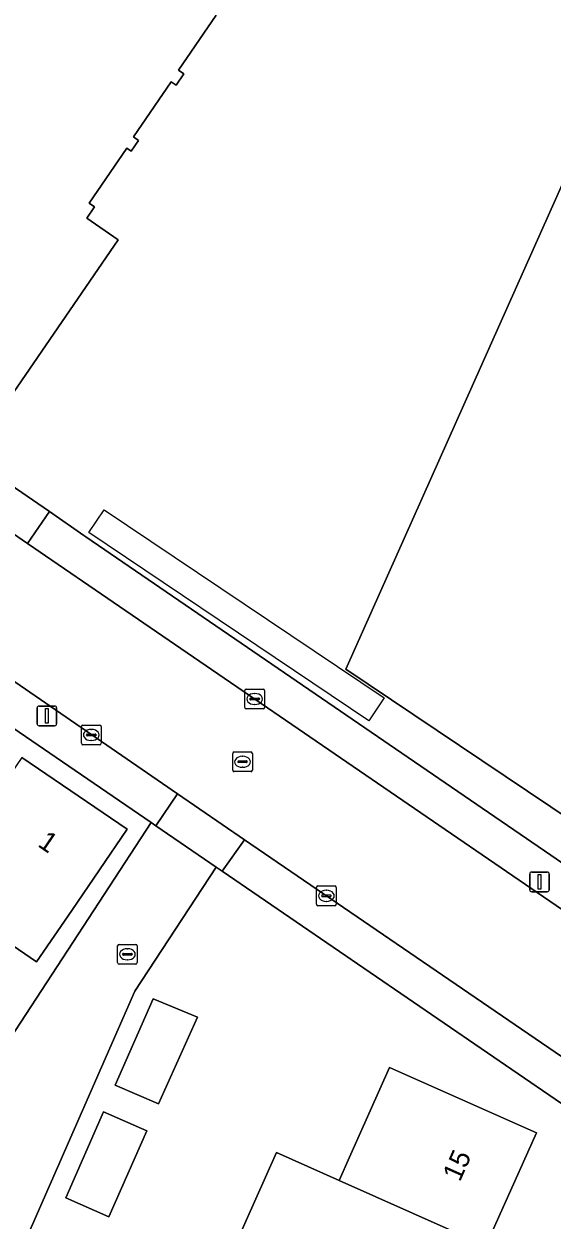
# Model space of a CAD drawing. Extents: x 160023 to 161302, y 384750 to 385707.
# Drawn here: x 160123.2 to 160150, y 385310.5 to 385371.2 of the extents above; entities that cross this region are included whole.
import ezdxf

# ---------------------------------------------------------------- set-up
doc = ezdxf.new("R2010")
doc.units = 0
for name, color, linetype in [('IMGEO_Erf', 7, 'Continuous'), ('IMGEO_Kolk', 7, 'Continuous'), ('IMGEO_Lichtmast', 7, 'Continuous'), ('IMGEO_Muur', 7, 'Continuous'), ('IMGEO_Pand', 7, 'Continuous'), ('IMGEO_Pand_nummerreeks', 7, 'Continuous'), ('IMGEO_Rijbaan_lokaal_open', 7, 'Continuous'), ('IMGEO_Rioolput', 7, 'Continuous'), ('IMGEO_Voetpad_open', 7, 'Continuous')]:
    doc.layers.add(name, color=color, linetype=linetype)

msp = doc.modelspace()

# ---------------------------------------------------------------- linework, layer by layer
at = {"layer": 'IMGEO_Erf'}
for points in [[(160132.919, 385371.685), (160131.005, 385368.893), (160131.279, 385368.705), (160130.884, 385368.13), (160130.634, 385368.301), (160128.713, 385365.499), (160128.973, 385365.32), (160128.601, 385364.779), (160128.386, 385364.926), (160126.471, 385362.132), (160126.738, 385361.949), (160126.341, 385361.37), (160127.943, 385360.271), (160122.625, 385352.516), (160109.571, 385361.468), (160114.265, 385368.313), (160113.654, 385368.732), (160114.009, 385369.25), (160112.687, 385370.157), (160124.902, 385387.961)], [(160093.406, 385374.95), (160103.841, 385367.794), (160103.323, 385367.037), (160102.919, 385366.448), (160100.498, 385362.918), (160105.594, 385359.428), (160120.662, 385349.43), (160120.442, 385349.221), (160124.446, 385346.473), (160126.203, 385345.256), (160126.296, 385345.192), (160149.901, 385329.017), (160154.104, 385326.136), (160157.93, 385334.826), (160155.989, 385335.681), (160153.709, 385336.675), (160151.041, 385330.714), (160139.497, 385338.47), (160150.705, 385363.58)], [(160118.455, 385313.614), (160129.62, 385330.68), (160087.038, 385359.824)], [(160123.055, 385333.992), (160128.399, 385330.342), (160125.58, 385326.215), (160123.798, 385323.607), (160120.717, 385325.711)], [(160152.014, 385315.353), (160133.213, 385328.221), (160132.92, 385328.421), (160128.791, 385322.11), (160120.909, 385304.204), (160118.514, 385298.764), (160117.264, 385295.926), (160116.015, 385293.089), (160114.766, 385290.253), (160113.701, 385287.743), (160114.618, 385287.345), (160116.68, 385286.451), (160114.754, 385282.009), (160113.13, 385278.262), (160115.091, 385275.318), (160112.419, 385273.539), (160114.46, 385270.474), (160117.839, 385265.396), (160112.507, 385262.087), (160109.628, 385266.727), (160106.437, 385271.869)], [(160133.385, 385308.118), (160135.973, 385313.924), (160139.16, 385312.503), (160139.685, 385313.681), (160141.719, 385318.246), (160149.173, 385314.924), (160146.613, 385309.181)]]:
    msp.add_lwpolyline(points, dxfattribs=at)
for points in [[(160129.712, 385321.73), (160131.965, 385320.799), (160129.993, 385316.404), (160127.791, 385317.345)], [(160127.192, 385315.989), (160129.39, 385315.025), (160127.473, 385310.658), (160125.275, 385311.622)]]:
    msp.add_lwpolyline(points, close=True, dxfattribs=at)
at = {"layer": 'IMGEO_Kolk'}
for p, q in [((160134.369, 385336.53), (160134.369, 385337.382)), ((160134.444, 385337.456), (160135.296, 385337.456)), ((160134.857, 385337.236), (160134.882, 385337.236)), ((160135.37, 385337.382), (160135.37, 385336.53)), ((160134.628, 385336.95), (160134.628, 385336.962)), ((160135.066, 385336.913), (160134.668, 385336.913)), ((160134.671, 385336.999), (160135.069, 385336.999)), ((160134.88, 385336.676), (160134.855, 385336.676)), ((160135.112, 385336.962), (160135.112, 385336.95)), ((160135.296, 385336.456), (160134.444, 385336.456)), ((160126.071, 385334.705), (160126.071, 385335.557)), ((160126.146, 385335.631), (160126.998, 385335.631)), ((160126.559, 385335.411), (160126.584, 385335.411)), ((160127.072, 385335.557), (160127.072, 385334.705)), ((160126.33, 385335.125), (160126.33, 385335.137)), ((160126.768, 385335.088), (160126.37, 385335.088)), ((160126.373, 385335.174), (160126.771, 385335.174)), ((160126.582, 385334.851), (160126.557, 385334.851)), ((160126.814, 385335.137), (160126.814, 385335.125)), ((160126.998, 385334.631), (160126.146, 385334.631)), ((160138.009, 385326.534), (160138.009, 385327.386)), ((160138.084, 385327.46), (160138.936, 385327.46)), ((160138.268, 385326.954), (160138.268, 385326.966)), ((160138.706, 385326.917), (160138.308, 385326.917)), ((160138.311, 385327.003), (160138.709, 385327.003)), ((160138.497, 385327.24), (160138.522, 385327.24)), ((160138.752, 385326.966), (160138.752, 385326.954)), ((160139.01, 385327.386), (160139.01, 385326.534)), ((160138.936, 385326.46), (160138.084, 385326.46)), ((160138.52, 385326.68), (160138.495, 385326.68)), ((160127.983, 385324.492), (160128.835, 385324.492)), ((160127.908, 385323.566), (160127.908, 385324.418)), ((160128.167, 385323.986), (160128.167, 385323.998)), ((160128.605, 385323.949), (160128.207, 385323.949)), ((160128.21, 385324.035), (160128.608, 385324.035)), ((160128.396, 385324.272), (160128.421, 385324.272)), ((160128.651, 385323.998), (160128.651, 385323.986)), ((160128.909, 385324.418), (160128.909, 385323.566)), ((160128.835, 385323.492), (160127.983, 385323.492)), ((160128.419, 385323.712), (160128.394, 385323.712))]:
    msp.add_line(p, q, dxfattribs=at)
for points in [[(160134.369, 385336.53), (160134.369, 385337.382)], [(160134.444, 385337.456), (160135.296, 385337.456)], [(160135.37, 385337.382), (160135.37, 385336.53)], [(160135.296, 385336.456), (160134.444, 385336.456)], [(160126.071, 385334.705), (160126.071, 385335.557)], [(160126.146, 385335.631), (160126.998, 385335.631)], [(160127.072, 385335.557), (160127.072, 385334.705)], [(160126.998, 385334.631), (160126.146, 385334.631)], [(160138.009, 385326.534), (160138.009, 385327.386)], [(160138.084, 385327.46), (160138.936, 385327.46)], [(160139.01, 385327.386), (160139.01, 385326.534)], [(160138.936, 385326.46), (160138.084, 385326.46)], [(160127.983, 385324.492), (160128.835, 385324.492)], [(160127.908, 385323.566), (160127.908, 385324.418)], [(160128.909, 385324.418), (160128.909, 385323.566)], [(160128.835, 385323.492), (160127.983, 385323.492)]]:
    msp.add_lwpolyline(points, dxfattribs=at)
for centre, radius, start, end in [((160134.446, 385337.38), 0.0765, 91.55205, 178.44795), ((160134.446, 385337.38), 0.0765, 91.55205, 178.44795), ((160135.294, 385337.38), 0.0765, 1.55205, 88.44795), ((160135.294, 385337.38), 0.0765, 1.55205, 88.44795), ((160134.668, 385336.959), 0.0403, 85.87752, 175.75265), ((160134.665, 385336.949), 0.0366, 178.93798, 274.71019), ((160135.069, 385336.956), 0.043, 264.86636, 352.45326), ((160135.073, 385336.961), 0.0386, 1.73085, 96.63898), ((160134.446, 385336.532), 0.0765, 181.55205, 268.44795), ((160134.446, 385336.532), 0.0765, 181.55205, 268.44795), ((160135.294, 385336.532), 0.0765, 271.55205, 358.44795), ((160135.294, 385336.532), 0.0765, 271.55205, 358.44795), ((160126.148, 385335.555), 0.0765, 91.55205, 178.44795), ((160126.148, 385335.555), 0.0765, 91.55205, 178.44795), ((160126.996, 385335.555), 0.0765, 1.55205, 88.44795), ((160126.996, 385335.555), 0.0765, 1.55205, 88.44795), ((160126.37, 385335.134), 0.0403, 85.87752, 175.75265), ((160126.367, 385335.124), 0.0366, 178.93798, 274.71019), ((160126.771, 385335.131), 0.043, 264.86636, 352.45326), ((160126.775, 385335.136), 0.0386, 1.73085, 96.63898), ((160126.148, 385334.707), 0.0765, 181.55205, 268.44795), ((160126.148, 385334.707), 0.0765, 181.55205, 268.44795), ((160126.996, 385334.707), 0.0765, 271.55205, 358.44795), ((160126.996, 385334.707), 0.0765, 271.55205, 358.44795), ((160138.086, 385327.384), 0.0765, 91.55205, 178.44795), ((160138.086, 385327.384), 0.0765, 91.55205, 178.44795), ((160138.308, 385326.963), 0.0403, 85.87752, 175.75265), ((160138.305, 385326.953), 0.0366, 178.93798, 274.71019), ((160138.709, 385326.96), 0.043, 264.86636, 352.45326), ((160138.713, 385326.965), 0.0386, 1.73085, 96.63898), ((160138.934, 385327.384), 0.0765, 1.55205, 88.44795), ((160138.934, 385327.384), 0.0765, 1.55205, 88.44795), ((160138.086, 385326.536), 0.0765, 181.55205, 268.44795), ((160138.086, 385326.536), 0.0765, 181.55205, 268.44795), ((160138.934, 385326.536), 0.0765, 271.55205, 358.44795), ((160138.934, 385326.536), 0.0765, 271.55205, 358.44795), ((160127.985, 385324.416), 0.0765, 91.55205, 178.44795), ((160127.985, 385324.416), 0.0765, 91.55205, 178.44795), ((160128.833, 385324.416), 0.0765, 1.55205, 88.44795), ((160128.833, 385324.416), 0.0765, 1.55205, 88.44795), ((160128.207, 385323.995), 0.0403, 85.87752, 175.75265), ((160128.204, 385323.985), 0.0366, 178.93798, 274.71019), ((160128.608, 385323.992), 0.043, 264.86636, 352.45326), ((160128.612, 385323.997), 0.0386, 1.73085, 96.63898), ((160127.985, 385323.568), 0.0765, 181.55205, 268.44795), ((160127.985, 385323.568), 0.0765, 181.55205, 268.44795), ((160128.833, 385323.568), 0.0765, 271.55205, 358.44795), ((160128.833, 385323.568), 0.0765, 271.55205, 358.44795)]:
    msp.add_arc(centre, radius, start, end, dxfattribs=at)
for centre, major_axis, ratio, start_param, end_param in [((160134.856, 385336.956), (-0.387, 0.002), 0.722429, 4.712389, 7.853982), ((160134.881, 385336.956), (-0.39, 0.002), 0.717154, 1.570796, 4.712389), ((160126.558, 385335.131), (-0.387, 0.002), 0.722429, 4.712389, 7.853982), ((160126.583, 385335.131), (-0.39, 0.002), 0.717154, 1.570796, 4.712389), ((160138.496, 385326.96), (-0.387, 0.002), 0.722429, 4.712389, 7.853982), ((160138.521, 385326.96), (-0.39, 0.002), 0.717154, 1.570796, 4.712389), ((160128.395, 385323.992), (-0.387, 0.002), 0.722429, 4.712389, 7.853982), ((160128.42, 385323.992), (-0.39, 0.002), 0.717154, 1.570796, 4.712389)]:
    msp.add_ellipse(centre, major_axis=major_axis, ratio=ratio, start_param=start_param, end_param=end_param, dxfattribs=at)
at = {"layer": 'IMGEO_Lichtmast'}
for p, q in [((160123.922, 385336.6), (160124.712, 385336.6)), ((160124.712, 385336.6), (160123.922, 385336.6)), ((160123.822, 385335.7), (160123.822, 385336.5)), ((160123.822, 385336.5), (160123.822, 385335.7)), ((160124.812, 385336.5), (160124.812, 385335.7)), ((160124.812, 385335.7), (160124.812, 385336.5)), ((160124.712, 385335.6), (160123.922, 385335.6)), ((160123.922, 385335.6), (160124.712, 385335.6)), ((160148.936, 385328.166), (160149.726, 385328.166)), ((160149.726, 385328.166), (160148.936, 385328.166)), ((160148.836, 385327.266), (160148.836, 385328.066)), ((160148.836, 385328.066), (160148.836, 385327.266)), ((160149.826, 385328.066), (160149.826, 385327.266)), ((160149.826, 385327.266), (160149.826, 385328.066)), ((160149.726, 385327.166), (160148.936, 385327.166)), ((160148.936, 385327.166), (160149.726, 385327.166))]:
    msp.add_line(p, q, dxfattribs=at)
for points in [[(160124.242, 385336.475), (160124.392, 385336.475), (160124.392, 385335.725), (160124.242, 385335.725), (160124.242, 385336.475)], [(160149.256, 385328.041), (160149.406, 385328.041), (160149.406, 385327.291), (160149.256, 385327.291), (160149.256, 385328.041)]]:
    msp.add_lwpolyline(points, dxfattribs=at)
for centre, start, end in [((160123.922, 385336.5), 90, 180), ((160123.922, 385336.5), 90, 180), ((160124.712, 385336.5), 0, 90), ((160124.712, 385336.5), 360, 90), ((160123.922, 385335.7), 180, 270), ((160123.922, 385335.7), 180, 270), ((160124.712, 385335.7), 270, 0), ((160124.712, 385335.7), 270, 0), ((160148.936, 385328.066), 90, 180), ((160148.936, 385328.066), 90, 180), ((160149.726, 385328.066), 0, 90), ((160149.726, 385328.066), 360, 90), ((160148.936, 385327.266), 180, 270), ((160148.936, 385327.266), 180, 270), ((160149.726, 385327.266), 270, 0), ((160149.726, 385327.266), 270, 0)]:
    msp.add_arc(centre, 0.1, start, end, dxfattribs=at)
at = {"layer": 'IMGEO_Muur'}
msp.add_lwpolyline([(160126.443, 385345.408), (160127.221, 385346.565), (160141.446, 385337.008), (160140.668, 385335.851), (160126.443, 385345.408)], dxfattribs=at)
at = {"layer": 'IMGEO_Pand'}
for points in [[(160169.658, 385377.498), (160171.975, 385382.642), (160162.094, 385389.268), (160153.298, 385369.433), (160154.24, 385369.015), (160151.647, 385363.162), (160150.705, 385363.58), (160139.497, 385338.47), (160151.041, 385330.714), (160153.709, 385336.675), (160155.989, 385335.681), (160165.448, 385357.005), (160163.123, 385358.056), (160171.47, 385376.693)], [(160128.399, 385330.342), (160123.055, 385333.992), (160118.457, 385327.259), (160117.949, 385326.515), (160118.047, 385326.448), (160120.211, 385324.97), (160120.717, 385325.711), (160123.798, 385323.607), (160125.58, 385326.215)], [(160131.965, 385320.799), (160129.712, 385321.73), (160127.791, 385317.345), (160129.993, 385316.404)], [(160139.16, 385312.503), (160146.613, 385309.181), (160149.173, 385314.924), (160141.719, 385318.246), (160139.685, 385313.681)], [(160129.39, 385315.025), (160127.192, 385315.989), (160125.275, 385311.622), (160127.473, 385310.658)], [(160146.613, 385309.181), (160139.16, 385312.503), (160135.973, 385313.924), (160133.385, 385308.118), (160136.572, 385306.698), (160144.026, 385303.376)]]:
    msp.add_lwpolyline(points, close=True, dxfattribs=at)
msp.add_lwpolyline([(160124.902, 385387.961), (160112.687, 385370.157), (160114.009, 385369.25), (160113.654, 385368.732), (160114.265, 385368.313), (160109.571, 385361.468), (160122.625, 385352.516), (160127.943, 385360.271), (160126.341, 385361.37), (160126.738, 385361.949), (160126.471, 385362.132), (160128.386, 385364.926), (160128.601, 385364.779), (160128.973, 385365.32), (160128.713, 385365.499), (160130.634, 385368.301), (160130.884, 385368.13), (160131.279, 385368.705), (160131.005, 385368.893), (160132.919, 385371.685)], dxfattribs=at)
at = {"layer": 'IMGEO_Rijbaan_lokaal_open'}
for points in [[(160154.329, 385323.627), (160153.286, 385324.341), (160123.334, 385344.855), (160118.796, 385347.963), (160118.151, 385348.405), (160076.337, 385377.118), (160072.906, 385372.103), (160130.948, 385332.139), (160134.348, 385329.812), (160152.796, 385317.185)], [(160120.909, 385304.204), (160128.791, 385322.11), (160132.92, 385328.421), (160129.854, 385330.52), (160129.62, 385330.68), (160118.455, 385313.614), (160117.632, 385314.182), (160114.231, 385309.25), (160111.84, 385310.899), (160109.45, 385312.547), (160107.06, 385314.196), (160104.669, 385315.844), (160102.278, 385317.493), (160099.888, 385319.142), (160097.498, 385320.79), (160095.107, 385322.439), (160092.716, 385324.087), (160090.326, 385325.736), (160086.537, 385320.243), (160084.441, 385317.204), (160085.838, 385314.953), (160087.437, 385312.376), (160089.036, 385309.8)]]:
    msp.add_lwpolyline(points, dxfattribs=at)
at = {"layer": 'IMGEO_Rioolput'}
for p, q in [((160133.753, 385333.34), (160133.753, 385334.192)), ((160133.828, 385334.266), (160134.68, 385334.266)), ((160134.754, 385334.192), (160134.754, 385333.34)), ((160134.012, 385333.76), (160134.012, 385333.772)), ((160134.45, 385333.723), (160134.052, 385333.723)), ((160134.055, 385333.809), (160134.453, 385333.809)), ((160134.241, 385334.046), (160134.266, 385334.046)), ((160134.496, 385333.772), (160134.496, 385333.76)), ((160134.68, 385333.266), (160133.828, 385333.266)), ((160134.264, 385333.486), (160134.239, 385333.486))]:
    msp.add_line(p, q, dxfattribs=at)
for points in [[(160133.753, 385333.34), (160133.753, 385334.192)], [(160133.828, 385334.266), (160134.68, 385334.266)], [(160134.754, 385334.192), (160134.754, 385333.34)], [(160134.68, 385333.266), (160133.828, 385333.266)]]:
    msp.add_lwpolyline(points, dxfattribs=at)
for centre, radius, start, end in [((160133.83, 385334.19), 0.0765, 91.55205, 178.44795), ((160133.83, 385334.19), 0.0765, 91.55205, 178.44795), ((160134.678, 385334.19), 0.0765, 1.55205, 88.44795), ((160134.678, 385334.19), 0.0765, 1.55205, 88.44795), ((160134.052, 385333.769), 0.0403, 85.87752, 175.75265), ((160134.049, 385333.759), 0.0366, 178.93798, 274.71019), ((160134.453, 385333.766), 0.043, 264.86636, 352.45326), ((160134.457, 385333.771), 0.0386, 1.73085, 96.63898), ((160133.83, 385333.342), 0.0765, 181.55205, 268.44795), ((160133.83, 385333.342), 0.0765, 181.55205, 268.44795), ((160134.678, 385333.342), 0.0765, 271.55205, 358.44795), ((160134.678, 385333.342), 0.0765, 271.55205, 358.44795)]:
    msp.add_arc(centre, radius, start, end, dxfattribs=at)
for centre, major_axis, ratio, start_param, end_param in [((160134.24, 385333.766), (-0.387, 0.002), 0.722429, 4.712389, 7.853982), ((160134.265, 385333.766), (-0.39, 0.002), 0.717154, 1.570796, 4.712389)]:
    msp.add_ellipse(centre, major_axis=major_axis, ratio=ratio, start_param=start_param, end_param=end_param, dxfattribs=at)
at = {"layer": 'IMGEO_Voetpad_open'}
for points in [[(160072.906, 385372.103), (160071.027, 385370.783), (160071.709, 385370.322), (160074.263, 385368.593), (160081.559, 385363.574), (160087.038, 385359.824), (160129.62, 385330.68), (160129.854, 385330.52), (160130.948, 385332.139)], [(160118.796, 385347.963), (160123.334, 385344.855), (160124.446, 385346.473), (160120.442, 385349.221), (160119.906, 385349.578)], [(160149.901, 385329.017), (160126.296, 385345.192), (160126.203, 385345.256), (160124.446, 385346.473), (160123.334, 385344.855), (160153.286, 385324.341), (160154.329, 385323.627), (160157.711, 385327.115), (160154.293, 385326.006), (160154.104, 385326.136)], [(160129.854, 385330.52), (160132.92, 385328.421), (160133.213, 385328.221), (160134.348, 385329.812), (160130.948, 385332.139)], [(160134.348, 385329.812), (160133.213, 385328.221), (160152.014, 385315.353), (160152.796, 385317.185)]]:
    msp.add_lwpolyline(points, close=True, dxfattribs=at)

# ---------------------------------------------------------------- texts
at = {"layer": 'IMGEO_Pand_nummerreeks'}
for s, rotation, p in [('1', 325.66264, (160123.807, 385329.506)), ('15', 65.97617, (160145.288, 385312.399))]:
    msp.add_text(s, height=1, rotation=rotation, dxfattribs=at).set_placement(p)

doc.saveas('drawing.dxf')
